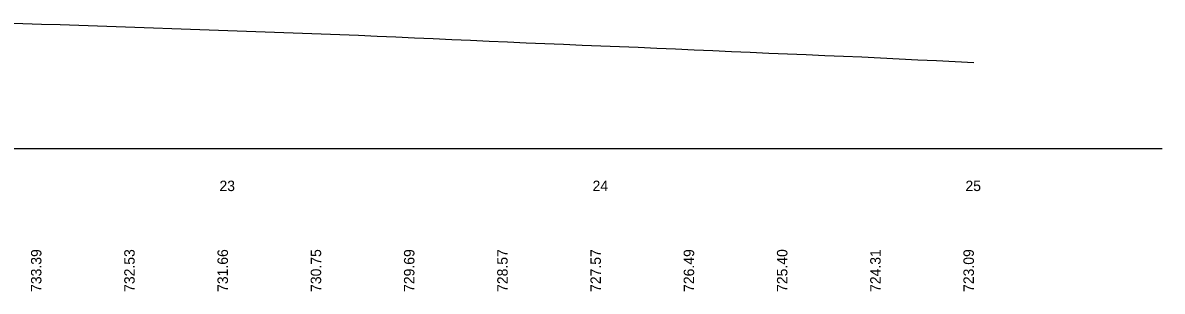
# Model space of a CAD drawing. Extents: x -434 to 1339, y -871 to 603.
# Drawn here: x 745 to 1050.5, y -38.2 to 33.7 of the extents above; entities that cross this region are included whole.
import ezdxf

# ---------------------------------------------------------------- set-up
doc = ezdxf.new("R2010")
doc.units = 0
for name, color, linetype in [('Default', 7, 'Continuous'), ('GK_Cells', 7, 'Continuous'), ('PF_P_Sta_Elev_Text', 7, 'Continuous'), ('SC_Scratch2', 7, 'Continuous'), ('XS_X_Ground_Line', 7, 'Continuous')]:
    doc.layers.add(name, color=color, linetype=linetype)

msp = doc.modelspace()

# ---------------------------------------------------------------- linework, layer by layer
at = {"layer": 'Default'}
msp.add_line((0, 0), (1050.49, 0), dxfattribs=at)
at = {"layer": 'GK_Cells'}
msp.add_line((0, 0), (1000, 0), dxfattribs=at)
at = {"layer": 'SC_Scratch2'}
msp.add_lwpolyline([(740, 33.71), (745, 33.56), (750, 33.39), (755, 33.22), (760, 33.04), (765, 32.87), (770, 32.7), (775, 32.53), (780, 32.36), (785, 32.19), (790, 32.02), (795, 31.84), (800, 31.66), (805, 31.47), (810, 31.29), (815, 31.11), (820, 30.93), (825, 30.75), (830, 30.56), (835, 30.38), (840, 30.15), (845, 29.92), (850, 29.69), (855, 29.46), (860, 29.24), (865, 29.02), (870, 28.8), (875, 28.57), (880, 28.35), (885, 28.15), (890, 27.96), (895, 27.76), (900, 27.57), (905, 27.37), (910, 27.16), (915, 26.94), (920, 26.72), (925, 26.49), (930, 26.27), (935, 26.05), (940, 25.82), (945, 25.61), (950, 25.4), (955, 25.2), (960, 24.99), (965, 24.78), (970, 24.55), (975, 24.31), (980, 24.07), (985, 23.82), (990, 23.58), (995, 23.34), (1000, 23.09)], dxfattribs=at)
at = {"layer": 'XS_X_Ground_Line'}
msp.add_lwpolyline([(740, 33.71), (745, 33.56), (750, 33.39), (755, 33.22), (760, 33.04), (765, 32.87), (770, 32.7), (775, 32.53), (780, 32.36), (785, 32.19), (790, 32.02), (795, 31.84), (800, 31.66), (805, 31.47), (810, 31.29), (815, 31.11), (820, 30.93), (825, 30.75), (830, 30.56), (835, 30.38), (840, 30.15), (845, 29.92), (850, 29.69), (855, 29.46), (860, 29.24), (865, 29.02), (870, 28.8), (875, 28.57), (880, 28.35), (885, 28.15), (890, 27.96), (895, 27.76), (900, 27.57), (905, 27.37), (910, 27.16), (915, 26.94), (920, 26.72), (925, 26.49), (930, 26.27), (935, 26.05), (940, 25.82), (945, 25.61), (950, 25.4), (955, 25.2), (960, 24.99), (965, 24.78), (970, 24.55), (975, 24.31), (980, 24.07), (985, 23.82), (990, 23.58), (995, 23.34), (1000, 23.09)], dxfattribs=at)

# ---------------------------------------------------------------- texts
at = {"layer": 'Default'}
for s, p in [('733.39', (750, -38.43)), ('732.53', (775, -38.43)), ('731.66', (800, -38.43)), ('730.75', (825, -38.43)), ('729.69', (850, -38.43)), ('728.57', (875, -38.43)), ('727.57', (900, -38.43)), ('726.49', (925, -38.43)), ('725.40', (950, -38.43)), ('724.31', (975, -38.43)), ('723.09', (1000, -38.43))]:
    msp.add_text(s, height=2.8, rotation=90, dxfattribs=at).set_placement(p)
at = {"layer": 'PF_P_Sta_Elev_Text'}
for s, p in [('23', (797.73, -11.4)), ('24', (897.77, -11.4)), ('25', (997.74, -11.4))]:
    msp.add_text(s, height=2.8, dxfattribs=at).set_placement(p)

doc.saveas('drawing.dxf')
